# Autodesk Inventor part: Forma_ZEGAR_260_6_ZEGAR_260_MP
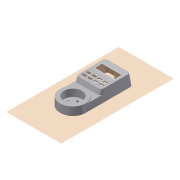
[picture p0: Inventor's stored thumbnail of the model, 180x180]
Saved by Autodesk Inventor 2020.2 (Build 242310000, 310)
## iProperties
Created: 2015-01
Part Number: Forma_ZEGAR_260_6_ZEGAR_260_MP
Material: Ogólny
Document SubType Name: Modeling
Designer: F.Stasiak
Density: 1 g/cm^3
Appearance: Domyślna
Catalog Web Link: www.expertbooks.pl
Manager: www.cadconsulting.pl
Company: Fabian Stasiak CAD Consulting
Author: F.Stasiak
Subject: Zbiór ćwiczeń. Autodesk Inventor 2020. Kurs Professional
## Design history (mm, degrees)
derived "ZEGAR_260.ipt"
node "Forma_ZEGAR_260_4_ZEGAR_260_WP"
feature "Zamknij obwiednię1" dims "d7" = 5, "d8" = 5, "d9" = 5, "d10" = 5, "d11" = 0
feature "Zamknij obwiednię2" dims "d12" = 5, "d13" = 5, "d14" = 5, "d15" = 5, "d16" = 0
feature "Zamknij obwiednię3" dims "d17" = 5, "d18" = 5, "d19" = 5, "d20" = 5, "d21" = 5, "d22" = 5, "d23" = 5, "d24" = 5, "d25" = 0
feature "Zamknij obwiednię4" dims "d26" = 5, "d27" = 5, "d28" = 5, "d29" = 5, "d30" = 0
feature "Zamknij obwiednię5" dims "d31" = 5, "d32" = 5, "d33" = 5, "d34" = 5, "d35" = 0
feature "Zamknij obwiednię6" dims "d36" = 5, "d37" = 5, "d38" = 5, "d39" = 5, "d40" = 0
feature "Zamknij obwiednię7" dims "d41" = 5, "d42" = 5, "d43" = 5, "d44" = 5, "d45" = 0
feature "Zamknij obwiednię8" dims "d46" = 5, "d47" = 5, "d48" = 5, "d49" = 5, "d50" = 0
feature "Zamknij obwiednię9" dims "d51" = 5, "d52" = 5, "d53" = 5, "d54" = 5, "d55" = 0
feature "Zamknij obwiednię10" dims "d56" = 5, "d57" = 0
feature "Zamknij obwiednię11" dims "d58" = 5, "d59" = 0
feature "Zamknij obwiednię12" dims "d60" = 5, "d61" = 0
node "Płaszczyzna konstrukcyjna1"
sketch "Szkic1"
  geometry: L1 (30.835, -178.031)-(30.835, 61.969); L2 (30.835, 61.969)-(-86.165, 61.969); L3 (-86.165, 61.969)-(-86.165, -178.031); L4 (-86.165, -178.031)-(30.835, -178.031); L5 (0, 0)-(0, -94.499) reference; L6 (-55.33, -94.499)-(-55.33, 0) reference; L7 (-49.319, 6.101)-(-6.011, 6.101) reference; A1 r 27.665 centre (-27.665, -94.499) between (-55.33, -94.499) and (0, -94.499) reference; 3 further points; 2 other entities
  constraints: 8 end point, 2 other
  dimensions: "d62" = 58.5 horizontal distance of point (-27.665, -58.031) L1.end (= 1.5 x Xmax); "d63" = 120 vertical distance of point (-27.665, -58.031) L1.end (= 1.5 x Ymax); "d64" = 58.5 horizontal distance of point (-27.665, -58.031) L2.end (= -1.5 x Xmin); "d65" = 120 vertical distance of point (-27.665, -58.031) L2.end (= 1.5 x Ymax); "d66" = 58.5 horizontal distance of point (-27.665, -58.031) L3.end (= -1.5 x Xmin); "d67" = 120 vertical distance of point (-27.665, -58.031) L3.end (= -1.5 x Ymin); "d68" = 58.5 horizontal distance of point (-27.665, -58.031) L1.start (= 1.5 x Xmax); "d69" = 120 vertical distance of point (-27.665, -58.031) L1.start (= -1.5 x Ymin)
feature "Zamknij obwiednię13" sketch "Szkic1"
feature "Oddzielenie matrycy1"
node "Płaszczyzna konstrukcyjna2"
sketch "Szkic2"
  geometry: L1 (0, -78)-(-20.191, -78) reference; L2 (-20.191, -78)-(-20.191, 0) reference; L3 (-17.791, -39)-(-12.991, -39); L4 (-17.791, -39)-(-15.391, -39); L5 (-17.791, -39)-(-17.791, -29.75); L6 (-20.191, -48.25)-(-15.391, -48.25); L7 (-15.391, -48.25)-(-15.391, -29.75); L8 (-15.391, -29.75)-(-20.191, -29.75); L9 (-20.191, -29.75)-(-20.191, -48.25)
  constraints: 14 end point, 1 horizontal, 1 perpendicular, 2 other
  dimensions: "d71" = 39 distance from line of L1 L3.start; "d72" = 2.4 distance from line of L2 L3.start; "d73" = 0 distance between parallel lines of L3 L4; "d74" = 4.8 distance between parallel lines of L9 L7; "d75" = 18.5 distance between parallel lines of L8 L6
extrude "Wyciągnięcie proste1" new body sketch "Szkic2" stored distance "d76" = 0.13; taper "d77" = 0 deg
node "Płaszczyzna konstrukcyjna3"
sketch "Szkic3"
  geometry: L1 (0, -18.5)-(-4.8, -18.5) reference; L2 (-4.8, -18.5)-(-4.8, 0) reference; L3 (-1.8, -9.25)-(4.2, -9.25); L4 (-1.8, -9.25)-(1.2, -9.25); L5 (-1.8, -9.25)-(-1.8, 5.75); L6 (-4.8, -24.25)-(1.2, -24.25); L7 (1.2, -24.25)-(1.2, 5.75); L8 (1.2, 5.75)-(-4.8, 5.75); L9 (-4.8, 5.75)-(-4.8, -24.25)
  constraints: 14 end point, 1 horizontal, 1 perpendicular, 2 other
  dimensions: "d79" = 9.25 distance from line of L1 L3.start; "d80" = 3 distance from line of L2 L3.start; "d81" = 0 distance between parallel lines of L3 L4; "d82" = 6 distance between parallel lines of L9 L7; "d83" = 30 distance between parallel lines of L8 L6
extrude "Wyciągnięcie proste2" join sketch "Szkic3" distance "d84" = 8; taper "d85" = 0 deg
feature "Bryła1::ZEGAR_260.ipt"
tag "Bryła wyprowadzona1"
feature "Bryła1::Forma_ZEGAR_260_4_ZEGAR_260_WP"
tag "Bryła wyprowadzona2"
body "Srf1"
body "Srf2"
body "Srf3"
body "Srf4"
body "Srf5"
body "Srf6"
body "Srf7"
body "Srf8"
body "Srf9"
body "Srf10"
body "Srf11"
body "Srf12"
body "Srf13"
node "Bryła3"
node "Bryła4"
node "Bryła5"
node "Bryła1"
feature "ZEGAR_260.ipt_Bodies"
node "Bryła2"
feature "Forma_ZEGAR_260_4_ZEGAR_260_WP_Bodies"
other parameters: "d1" = 39, "d2" = 39, "d6" = 0, "Xmin" = -39, "Xmax" = 39, "d70" = 0, "d78" = 0
